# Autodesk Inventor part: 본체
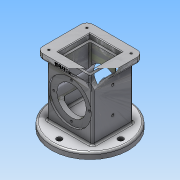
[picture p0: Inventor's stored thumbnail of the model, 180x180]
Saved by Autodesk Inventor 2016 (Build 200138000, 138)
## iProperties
Created: 2018-10
Part Number: 본체
Material: 알루미늄 6061
Document SubType Name: Modeling
Designer: Administrator
Density: 2.7 g/cm^3
Appearance: 알루미늄 - 평지
Mass: 984.575 g
Surface Area: 743.905 cm^2
Volume: 364.657 cm^3
Author: Administrator
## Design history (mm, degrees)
sketch "스케치1"
  geometry: C1 r 62.5 at (0, 0); 1 further point
  constraints: 1 centre point, 1 coincident
  dimensions: "d0" = 125 diameter of C1
extrude "돌출1" new body sketch "스케치1" distance "d1" = 10; taper "d2" = 0 deg
sketch "스케치2"
  geometry: L1 (-37, 33)-(37, 33); L2 (37, 33)-(37, -33); L3 (37, -33)-(-37, -33); L4 (-37, -33)-(-37, 33); L5 (-37, 33)-(37, -33); L6 (37, 33)-(-37, -33); 1 further point
  constraints: 12 end point, 2 midpoint, 2 parallel, 1 horizontal, 1 perpendicular
  dimensions: "d3" = 74 distance of L2.end L3.end; "d4" = 66 distance of L1.end L2.end
extrude "돌출2" join sketch "스케치2" distance "d5" = 88; taper "d6" = 0 deg
sketch "스케치3"
  geometry: L1 (-46, 41)-(46, 41); L2 (46, 41)-(46, -41); L3 (46, -41)-(-46, -41); L4 (-46, -41)-(-46, 41); L5 (-46, 41)-(46, -41); L6 (46, 41)-(-46, -41); 1 further point
  constraints: 12 end point, 2 midpoint, 2 parallel, 1 horizontal, 1 perpendicular
  dimensions: "d7" = 92 distance of L2.end L3.end; "d8" = 82 distance of L1.end L2.end
extrude "돌출3" join sketch "스케치3" distance "d9" = 10; taper "d10" = 0 deg
sketch "스케치4"
  geometry: L1 (-62.5, 0)-(62.5, 0) reference; L2 (0, 18)-(-24.826, 18); L3 (-24.826, 18)-(-28, 0); L4 (0, 0)-(-28, 0); L5 (0, 29.802)-(0, -5.8); 1 further point
  constraints: 8 end point, 3 point on line, 1 collinear, 1 parallel, 1 vertical
  dimensions: "d11" = 18 distance between parallel lines of L1 L2; "d12" = 80 deg angle of L1 L3; "d13" = 28 distance of point (0, 0) L3.end; "d14" = 125 diameter of L1.end L5
revolve "회전1" sketch "스케치4" stored, may be unused: angle "d15" = 90 deg
fillet "모깎기1" dims "d16" = 3
sketch "스케치5"
  geometry: L1 (-22, 22)-(22, 22); L2 (22, 22)-(22, -22); L3 (22, -22)-(-22, -22); L4 (-22, -22)-(-22, 22); L5 (-22, 22)-(22, -22); L6 (22, 22)-(-22, -22); 1 further point
  constraints: 12 end point, 2 midpoint, 2 parallel, 1 horizontal, 1 perpendicular
  dimensions: "d17" = 44 distance of L1.start L1.end; "d18" = 44 distance of L1.end L2.end
extrude "돌출4" cut sketch "스케치5" distance "d19" = 82; taper "d20" = 0 deg
sketch "스케치6"
  geometry: L1 (-26, 26)-(26, 26); L2 (26, 26)-(26, -26); L3 (26, -26)-(-26, -26); L4 (-26, -26)-(-26, 26); L5 (-26, 26)-(26, -26); L6 (26, 26)-(-26, -26); 1 further point
  constraints: 12 end point, 2 midpoint, 2 parallel, 1 horizontal, 1 perpendicular
  dimensions: "d21" = 52 distance of L2.end L3.end; "d22" = 52 distance of L1.end L2.end
extrude "돌출5" cut sketch "스케치6" distance "d23" = 8; taper "d24" = 0 deg
sketch "스케치7"
  geometry: L1 (0, 0)-(0, 88) reference; L2 (-25.5, -10)-(99.5, -10) reference; C1 r 24 at (37, 44); 1 further point
  constraints: 1 centre point
  dimensions: "d25" = 48 diameter of C1; "d26" = 37 distance from line of C1.centre L1; "d27" = 54 distance from line of L2 C1.centre
extrude "돌출6" cut sketch "스케치7" stored distance "d28" = 8; taper "d29" = 0 deg
sketch "스케치8"
  geometry: C1 r 35 at (37, 44); C2 r 24 at (37, 44) reference; 1 further point
  constraints: 1 centre point, 1 concentric
  dimensions: "d30" = 70 diameter of C1
extrude "돌출7" cut sketch "스케치8" distance "d31" = 3; taper "d32" = 0 deg
sketch "스케치9"
  geometry: C1 r 35 at (37, -44); C2 r 24 at (37, -44) reference; 1 further point
  constraints: 1 centre point, 1 concentric
  dimensions: "d33" = 70 diameter of C1
extrude "돌출8" cut sketch "스케치9" distance "d34" = 3; taper "d35" = 0 deg
sketch "스케치10" dims "d36" = 100
  geometry: 3 further points
  constraints: 2 vertical alignment, 1 coincident, 2 other
hole "구멍1" sketch "스케치10" at (0, 50) diameter "d37" = 9; stored, may be unused: countersink angle "d41" = 90 deg, drill point angle "d43" = 118 deg; dims "d38" = 6, "d39" = 4, "d40" = 2, "d42" = 8
sketch "스케치11" dims "d47" = 58
  geometry: C1 r 35 at (0, 0) reference; 3 further points
  constraints: 2 vertical alignment, 3 other
hole "구멍2" sketch "스케치11" at (0, 29) diameter "d48" = 3.242; stored, may be unused: countersink angle "d52" = 90 deg, drill point angle "d54" = 118 deg; dims "d49" = 4, "d50" = 4, "d51" = 2, "d53" = 6
fillet "모깎기2" dims "d58" = 10
sketch "스케치13"
  geometry: A1 r 10 centre (-36, -31) between (-46, -31) and (-36, -41) reference; A2 r 10 centre (-36, 31) between (-36, 41) and (-46, 31) reference; A3 r 10 centre (36, 31) between (46, 31) and (36, 41) reference; A4 r 10 centre (36, -31) between (36, -41) and (46, -31) reference; 5 further points
  constraints: 4 coincident
hole "구멍3" sketch "스케치13" at (-36, -31), (-36, 31), (36, 31), (36, -31) diameter "d59" = 3.242; stored, may be unused: countersink angle "d63" = 90 deg, drill point angle "d65" = 118 deg; dims "d60" = 4, "d61" = 4, "d62" = 2, "d64" = 6
sketch "스케치14"
  geometry: L1 (10, -29.5)-(10, 95.5) reference; 3 further points
  constraints: 1 horizontal alignment
  dimensions: "d66" = 37 distance from line of point (-27, 33) L1; "d67" = 43 distance of point (-27, 33) point (-70, 33); "d68" = 62.5 vertical distance of L1.start point (-27, 33)
hole "구멍4" sketch "스케치14" at (-70, 33), (-27, 33) diameter "d69" = 4.134; stored, may be unused: countersink angle "d73" = 90 deg, drill point angle "d75" = 118 deg; dims "d70" = 10, "d71" = 4, "d72" = 2, "d74" = 20
fillet "모깎기3" dims "d76" = 3
fillet "모깎기4" dims "d77" = 3
fillet "모깎기5" dims "d78" = 3
chamfer "모따기1" distance "d79" = 1; stored, may be unused: second distance "d80" = 2, angle "d81" = 45 deg
fillet "모깎기6" dims "d82" = 3
fillet "모깎기7" dims "d83" = 3
fillet "모깎기8" dims "d84" = 3
sketch "스케치15"
  geometry: L1 (-10, 0)-(-10, -7) reference; L2 (0, 0)-(72, 0) reference; 2 further points
  constraints: 1 other
  dimensions: "d85" = 46 distance from line of L1 point (36, -4); "d86" = 4 distance from line of L2 point (36, -4)
feature "엠보싱1" sketch "스케치15" dims "d87" = 0.5, "d88" = 0
sketch "스케치16"
  geometry: L1 (36, 9.808)-(112.569, 9.808); L2 (112.569, 9.808)-(112.569, -94.374); L3 (112.569, -94.374)-(36, -94.374); L4 (36, -94.374)-(36, 9.808); 1 further point
  constraints: 8 end point, 2 parallel, 1 horizontal, 1 perpendicular
extrude "돌출9" cut sketch "스케치16" stored distance "d89" = 10; taper "d90" = 0 deg
node "솔리드1"
pattern_circular "원형 패턴1" dims angle "d45" = 360 deg
pattern_circular "원형 패턴2" dims angle "d56" = 360 deg
mirror "대칭1"
